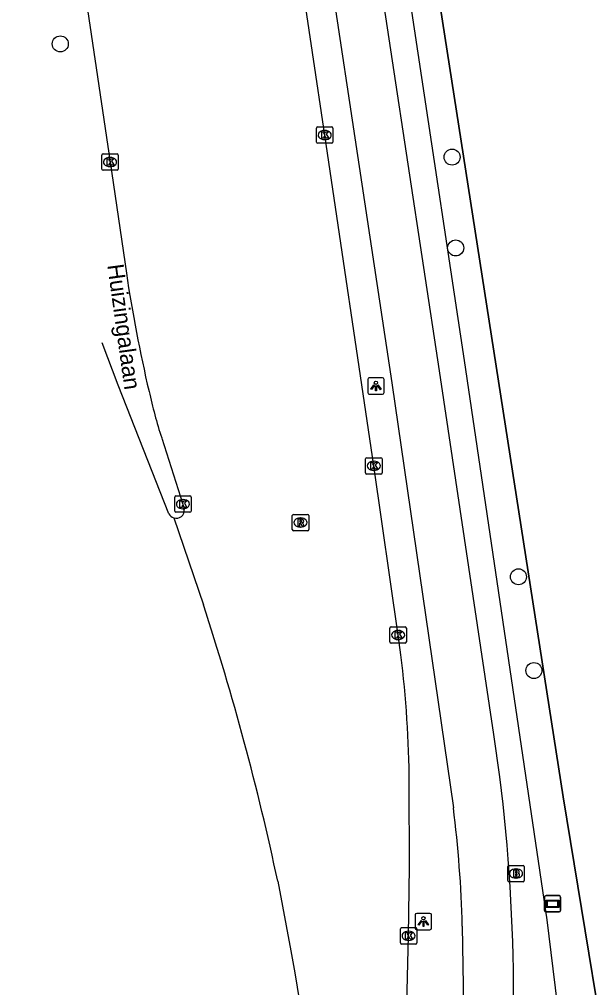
# Model space of a CAD drawing. Extents: x 159451 to 160663, y 388402 to 389723.
# Drawn here: x 159483.5 to 159518.3, y 388988.3 to 389047.5 of the extents above; entities that cross this region are included whole.
import ezdxf

# ---------------------------------------------------------------- set-up
doc = ezdxf.new("R2010")
doc.units = 0
for name, color, linetype in [('IMGEO_Boom', 7, 'Continuous'), ('IMGEO_Brandkraan', 7, 'Continuous'), ('IMGEO_Fietspad_gesloten', 7, 'Continuous'), ('IMGEO_Gemengd_bos', 7, 'Continuous'), ('IMGEO_Hek', 7, 'Continuous'), ('IMGEO_Kolk', 7, 'Continuous'), ('IMGEO_Lichtpunt', 7, 'Continuous'), ('IMGEO_Openbare_ruimte_label', 7, 'Continuous'), ('IMGEO_OVBaan_gesloten', 7, 'Continuous'), ('IMGEO_Rijbaan_regionaal_gesloten', 7, 'Continuous'), ('IMGEO_Rioolput', 7, 'Continuous'), ('IMGEO_Verklikker', 7, 'Continuous'), ('IMGEO_Voetpad_open', 7, 'Continuous')]:
    doc.layers.add(name, color=color, linetype=linetype)

msp = doc.modelspace()

# ---------------------------------------------------------------- linework, layer by layer
at = {"layer": 'IMGEO_Boom'}
for centre in [(159485.955, 389045.995), (159509.863, 389039.082), (159510.083, 389033.53), (159513.916, 389013.444), (159514.857, 389007.717)]:
    msp.add_circle(centre, 0.489, dxfattribs=at)
at = {"layer": 'IMGEO_Brandkraan'}
for p, q in [((159513.265, 388994.89), (159513.265, 388995.742)), ((159513.34, 388995.816), (159514.192, 388995.816)), ((159514.266, 388995.742), (159514.266, 388994.89)), ((159513.753, 388995.596), (159513.778, 388995.596)), ((159514.192, 388994.816), (159513.34, 388994.816)), ((159513.776, 388995.036), (159513.751, 388995.036))]:
    msp.add_line(p, q, dxfattribs=at)
for points in [[(159513.265, 388994.89), (159513.265, 388995.742)], [(159513.34, 388995.816), (159514.192, 388995.816)], [(159514.266, 388995.742), (159514.266, 388994.89)], [(159513.613, 388995.516), (159513.613, 388995.116), (159513.826, 388995.116)], [(159513.844, 388995.516), (159513.613, 388995.516)], [(159513.792, 388995.435), (159513.738, 388995.435), (159513.738, 388995.359)], [(159513.738, 388995.359), (159513.791, 388995.359)], [(159513.8, 388995.283), (159513.738, 388995.283), (159513.738, 388995.202)], [(159513.738, 388995.202), (159513.8, 388995.202)], [(159514.192, 388994.816), (159513.34, 388994.816)]]:
    msp.add_lwpolyline(points, dxfattribs=at)
for centre, radius, start, end in [((159513.342, 388995.74), 0.0765, 91.55205, 178.44795), ((159513.342, 388995.74), 0.0765, 91.55205, 178.44795), ((159514.19, 388995.74), 0.0765, 1.55205, 88.44795), ((159514.19, 388995.74), 0.0765, 1.55205, 88.44795), ((159513.793, 388995.397), 0.0379, 267.82845, 90.93552), ((159513.801, 388995.242), 0.0404, 269.87594, 90.50774), ((159513.848, 388995.371), 0.145, 59.4692, 91.53667), ((159513.873, 388995.418), 0.0922, 285.51372, 58.15012), ((159513.878, 388995.226), 0.105, 301.31148, 78.98903), ((159513.342, 388994.892), 0.0765, 181.55205, 268.44795), ((159513.342, 388994.892), 0.0765, 181.55205, 268.44795), ((159513.832, 388995.367), 0.251, 268.66757, 293.53466), ((159514.19, 388994.892), 0.0765, 271.55205, 358.44795), ((159514.19, 388994.892), 0.0765, 271.55205, 358.44795)]:
    msp.add_arc(centre, radius, start, end, dxfattribs=at)
for centre, major_axis, ratio, start_param, end_param in [((159513.752, 388995.316), (-0.387, 0.002), 0.722429, 4.712389, 7.853982), ((159513.777, 388995.316), (-0.39, 0.002), 0.717154, 1.570796, 4.712389)]:
    msp.add_ellipse(centre, major_axis=major_axis, ratio=ratio, start_param=start_param, end_param=end_param, dxfattribs=at)
at = {"layer": 'IMGEO_Fietspad_gesloten'}
for points in [[(159498.641, 389077.39), (159498.535, 389077.37), (159500.421, 389063.479), (159506.196, 389025.302), (159509.943, 388999.337)], [(159512.775, 389001.232), (159512.419, 389003.812), (159509.105, 389026.02), (159503.37, 389063.924), (159501.365, 389077.519)], [(159510.487, 388992.109), (159510.57, 388987.262), (159510.486, 388981.357), (159510.453, 388977.118), (159510.587, 388971.253)]]:
    msp.add_lwpolyline(points, dxfattribs=at)
for centre, radius, start, end in [((159405.559, 388987.753), 108.06, 0.01241, 7.16571), ((159438.669, 388990.338), 71.84, 1.4124, 7.19586)]:
    msp.add_arc(centre, radius, start, end, dxfattribs=at)
at = {"layer": 'IMGEO_Gemengd_bos'}
msp.add_lwpolyline([(159575.636, 389087.806), (159574.696, 389093.295), (159556.654, 389090.594), (159543.414, 389088.835), (159534.923, 389087.144), (159506.995, 389079.727), (159505.308, 389078.139), (159504.909, 389075.552), (159516.649, 389000), (159527.326, 388934.886), (159532.821, 388904.1), (159538.108, 388877.879)], dxfattribs=at)
at = {"layer": 'IMGEO_Hek'}
msp.add_lwpolyline([(159678.25, 388782.74), (159562.528, 388756.756), (159538.536, 388875.752), (159538.123, 388877.804), (159532.821, 388904.1), (159527.326, 388934.886), (159516.649, 389000), (159504.909, 389075.552), (159505.308, 389078.139), (159506.995, 389079.727), (159534.923, 389087.144), (159543.414, 389088.835), (159556.654, 389090.594), (159574.696, 389093.295)], dxfattribs=at)
at = {"layer": 'IMGEO_Kolk'}
for p, q in [((159501.589, 389040.004), (159501.589, 389040.856)), ((159501.664, 389040.93), (159502.516, 389040.93)), ((159502.077, 389040.71), (159502.102, 389040.71)), ((159502.59, 389040.856), (159502.59, 389040.004)), ((159502.1, 389040.15), (159502.075, 389040.15)), ((159502.516, 389039.93), (159501.664, 389039.93)), ((159488.489, 389038.355), (159488.489, 389039.207)), ((159488.564, 389039.281), (159489.416, 389039.281)), ((159488.977, 389039.061), (159489.002, 389039.061)), ((159489.49, 389039.207), (159489.49, 389038.355)), ((159489, 389038.501), (159488.975, 389038.501)), ((159489.416, 389038.281), (159488.564, 389038.281)), ((159504.588, 389019.794), (159504.588, 389020.646)), ((159504.663, 389020.72), (159505.515, 389020.72)), ((159505.589, 389020.646), (159505.589, 389019.794)), ((159505.076, 389020.5), (159505.101, 389020.5)), ((159505.515, 389019.72), (159504.663, 389019.72)), ((159505.099, 389019.94), (159505.074, 389019.94)), ((159492.939, 389017.457), (159492.939, 389018.309)), ((159493.014, 389018.383), (159493.866, 389018.383)), ((159493.94, 389018.309), (159493.94, 389017.457)), ((159493.427, 389018.163), (159493.452, 389018.163)), ((159493.866, 389017.383), (159493.014, 389017.383)), ((159493.45, 389017.603), (159493.425, 389017.603)), ((159506.072, 389009.461), (159506.072, 389010.313)), ((159506.147, 389010.387), (159506.999, 389010.387)), ((159506.56, 389010.167), (159506.585, 389010.167)), ((159507.073, 389010.313), (159507.073, 389009.461)), ((159506.999, 389009.387), (159506.147, 389009.387)), ((159506.583, 389009.607), (159506.558, 389009.607)), ((159506.708, 388991.083), (159506.708, 388991.935)), ((159506.783, 388992.009), (159507.635, 388992.009)), ((159507.196, 388991.789), (159507.221, 388991.789)), ((159507.709, 388991.935), (159507.709, 388991.083)), ((159507.635, 388991.009), (159506.783, 388991.009)), ((159507.219, 388991.229), (159507.194, 388991.229))]:
    msp.add_line(p, q, dxfattribs=at)
for points in [[(159501.589, 389040.004), (159501.589, 389040.856)], [(159501.664, 389040.93), (159502.516, 389040.93)], [(159502.59, 389040.856), (159502.59, 389040.004)], [(159501.91, 389040.63), (159502.033, 389040.63), (159502.033, 389040.479), (159502.163, 389040.63), (159502.327, 389040.63), (159502.181, 389040.479), (159502.334, 389040.23), (159502.182, 389040.23), (159502.097, 389040.394), (159502.033, 389040.327), (159502.033, 389040.23), (159501.91, 389040.23), (159501.91, 389040.63)], [(159502.516, 389039.93), (159501.664, 389039.93)], [(159488.489, 389038.355), (159488.489, 389039.207)], [(159488.564, 389039.281), (159489.416, 389039.281)], [(159488.81, 389038.981), (159488.933, 389038.981), (159488.933, 389038.83), (159489.063, 389038.981), (159489.227, 389038.981), (159489.081, 389038.83), (159489.234, 389038.581), (159489.082, 389038.581), (159488.997, 389038.745), (159488.933, 389038.678), (159488.933, 389038.581), (159488.81, 389038.581), (159488.81, 389038.981)], [(159489.49, 389039.207), (159489.49, 389038.355)], [(159489.416, 389038.281), (159488.564, 389038.281)], [(159504.588, 389019.794), (159504.588, 389020.646)], [(159504.663, 389020.72), (159505.515, 389020.72)], [(159505.589, 389020.646), (159505.589, 389019.794)], [(159504.909, 389020.42), (159505.032, 389020.42), (159505.032, 389020.269), (159505.162, 389020.42), (159505.326, 389020.42), (159505.18, 389020.269), (159505.333, 389020.02), (159505.181, 389020.02), (159505.096, 389020.184), (159505.032, 389020.117), (159505.032, 389020.02), (159504.909, 389020.02), (159504.909, 389020.42)], [(159505.515, 389019.72), (159504.663, 389019.72)], [(159492.939, 389017.457), (159492.939, 389018.309)], [(159493.014, 389018.383), (159493.866, 389018.383)], [(159493.94, 389018.309), (159493.94, 389017.457)], [(159493.26, 389018.083), (159493.383, 389018.083), (159493.383, 389017.932), (159493.513, 389018.083), (159493.677, 389018.083), (159493.531, 389017.932), (159493.684, 389017.683), (159493.532, 389017.683), (159493.447, 389017.847), (159493.383, 389017.78), (159493.383, 389017.683), (159493.26, 389017.683), (159493.26, 389018.083)], [(159493.866, 389017.383), (159493.014, 389017.383)], [(159506.072, 389009.461), (159506.072, 389010.313)], [(159506.147, 389010.387), (159506.999, 389010.387)], [(159506.393, 389010.087), (159506.516, 389010.087), (159506.516, 389009.936), (159506.646, 389010.087), (159506.81, 389010.087), (159506.664, 389009.936), (159506.817, 389009.687), (159506.665, 389009.687), (159506.58, 389009.851), (159506.516, 389009.784), (159506.516, 389009.687), (159506.393, 389009.687), (159506.393, 389010.087)], [(159507.073, 389010.313), (159507.073, 389009.461)], [(159506.999, 389009.387), (159506.147, 389009.387)], [(159506.708, 388991.083), (159506.708, 388991.935)], [(159506.783, 388992.009), (159507.635, 388992.009)], [(159507.029, 388991.709), (159507.152, 388991.709), (159507.152, 388991.558), (159507.282, 388991.709), (159507.446, 388991.709), (159507.3, 388991.558), (159507.453, 388991.309), (159507.301, 388991.309), (159507.216, 388991.473), (159507.152, 388991.406), (159507.152, 388991.309), (159507.029, 388991.309), (159507.029, 388991.709)], [(159507.709, 388991.935), (159507.709, 388991.083)], [(159507.635, 388991.009), (159506.783, 388991.009)]]:
    msp.add_lwpolyline(points, dxfattribs=at)
for centre, start, end in [((159501.666, 389040.854), 91.55205, 178.44795), ((159501.666, 389040.854), 91.55205, 178.44795), ((159502.514, 389040.854), 1.55205, 88.44795), ((159502.514, 389040.854), 1.55205, 88.44795), ((159501.666, 389040.006), 181.55205, 268.44795), ((159501.666, 389040.006), 181.55205, 268.44795), ((159502.514, 389040.006), 271.55205, 358.44795), ((159502.514, 389040.006), 271.55205, 358.44795), ((159488.566, 389039.205), 91.55205, 178.44795), ((159488.566, 389039.205), 91.55205, 178.44795), ((159489.414, 389039.205), 1.55205, 88.44795), ((159489.414, 389039.205), 1.55205, 88.44795), ((159488.566, 389038.357), 181.55205, 268.44795), ((159488.566, 389038.357), 181.55205, 268.44795), ((159489.414, 389038.357), 271.55205, 358.44795), ((159489.414, 389038.357), 271.55205, 358.44795), ((159504.665, 389020.644), 91.55205, 178.44795), ((159504.665, 389020.644), 91.55205, 178.44795), ((159505.513, 389020.644), 1.55205, 88.44795), ((159505.513, 389020.644), 1.55205, 88.44795), ((159504.665, 389019.796), 181.55205, 268.44795), ((159504.665, 389019.796), 181.55205, 268.44795), ((159505.513, 389019.796), 271.55205, 358.44795), ((159505.513, 389019.796), 271.55205, 358.44795), ((159493.016, 389018.307), 91.55205, 178.44795), ((159493.016, 389018.307), 91.55205, 178.44795), ((159493.864, 389018.307), 1.55205, 88.44795), ((159493.864, 389018.307), 1.55205, 88.44795), ((159493.016, 389017.459), 181.55205, 268.44795), ((159493.016, 389017.459), 181.55205, 268.44795), ((159493.864, 389017.459), 271.55205, 358.44795), ((159493.864, 389017.459), 271.55205, 358.44795), ((159506.149, 389010.311), 91.55205, 178.44795), ((159506.149, 389010.311), 91.55205, 178.44795), ((159506.997, 389010.311), 1.55205, 88.44795), ((159506.997, 389010.311), 1.55205, 88.44795), ((159506.149, 389009.463), 181.55205, 268.44795), ((159506.149, 389009.463), 181.55205, 268.44795), ((159506.997, 389009.463), 271.55205, 358.44795), ((159506.997, 389009.463), 271.55205, 358.44795), ((159506.785, 388991.933), 91.55205, 178.44795), ((159506.785, 388991.933), 91.55205, 178.44795), ((159507.633, 388991.933), 1.55205, 88.44795), ((159507.633, 388991.933), 1.55205, 88.44795), ((159506.785, 388991.085), 181.55205, 268.44795), ((159506.785, 388991.085), 181.55205, 268.44795), ((159507.633, 388991.085), 271.55205, 358.44795), ((159507.633, 388991.085), 271.55205, 358.44795)]:
    msp.add_arc(centre, 0.0765, start, end, dxfattribs=at)
for centre, major_axis, ratio, start_param, end_param in [((159502.076, 389040.43), (-0.387, 0.002), 0.722429, 4.712389, 7.853982), ((159502.101, 389040.43), (-0.39, 0.002), 0.717154, 1.570796, 4.712389), ((159488.976, 389038.781), (-0.387, 0.002), 0.722429, 4.712389, 7.853982), ((159489.001, 389038.781), (-0.39, 0.002), 0.717154, 1.570796, 4.712389), ((159505.075, 389020.22), (-0.387, 0.002), 0.722429, 4.712389, 7.853982), ((159505.1, 389020.22), (-0.39, 0.002), 0.717154, 1.570796, 4.712389), ((159493.426, 389017.883), (-0.387, 0.002), 0.722429, 4.712389, 7.853982), ((159493.451, 389017.883), (-0.39, 0.002), 0.717154, 1.570796, 4.712389), ((159506.559, 389009.887), (-0.387, 0.002), 0.722429, 4.712389, 7.853982), ((159506.584, 389009.887), (-0.39, 0.002), 0.717154, 1.570796, 4.712389), ((159507.195, 388991.509), (-0.387, 0.002), 0.722429, 4.712389, 7.853982), ((159507.22, 388991.509), (-0.39, 0.002), 0.717154, 1.570796, 4.712389)]:
    msp.add_ellipse(centre, major_axis=major_axis, ratio=ratio, start_param=start_param, end_param=end_param, dxfattribs=at)
at = {"layer": 'IMGEO_Lichtpunt'}
for p, q in [((159504.719, 389025.501), (159504.719, 389024.694)), ((159504.719, 389025.501), (159504.719, 389024.694)), ((159505.621, 389025.596), (159504.813, 389025.596)), ((159505.621, 389025.596), (159504.813, 389025.596)), ((159505.715, 389024.694), (159505.715, 389025.501)), ((159505.715, 389024.694), (159505.715, 389025.501)), ((159504.813, 389024.6), (159505.621, 389024.6)), ((159504.813, 389024.6), (159505.621, 389024.6)), ((159507.614, 388992.785), (159507.614, 388991.978)), ((159507.614, 388992.785), (159507.614, 388991.978)), ((159508.516, 388992.88), (159507.708, 388992.88)), ((159508.516, 388992.88), (159507.708, 388992.88)), ((159508.61, 388991.978), (159508.61, 388992.785)), ((159508.61, 388991.978), (159508.61, 388992.785)), ((159507.708, 388991.884), (159508.516, 388991.884)), ((159507.708, 388991.884), (159508.516, 388991.884))]:
    msp.add_line(p, q, dxfattribs=at)
for points in [[(159505.093, 389025.165), (159505.132, 389025.137), (159504.944, 389024.875), (159504.906, 389024.902), (159505.093, 389025.165)], [(159505.195, 389025.117), (159505.242, 389025.117), (159505.242, 389024.795), (159505.195, 389024.795), (159505.195, 389025.117)], [(159505.305, 389025.137), (159505.343, 389025.164), (159505.53, 389024.902), (159505.491, 389024.874), (159505.305, 389025.137)], [(159507.988, 388992.449), (159508.027, 388992.421), (159507.839, 388992.159), (159507.801, 388992.186), (159507.988, 388992.449)], [(159508.09, 388992.401), (159508.137, 388992.401), (159508.137, 388992.079), (159508.09, 388992.079), (159508.09, 388992.401)], [(159508.2, 388992.421), (159508.238, 388992.448), (159508.425, 388992.186), (159508.386, 388992.158), (159508.2, 388992.421)]]:
    msp.add_lwpolyline(points, dxfattribs=at)
for centre in [(159505.218, 389025.299), (159508.113, 388992.583)]:
    msp.add_circle(centre, 0.0994, dxfattribs=at)
for centre, start, end in [((159504.813, 389025.501), 90, 180), ((159504.813, 389025.501), 90, 180), ((159505.621, 389025.501), 0, 90), ((159505.621, 389025.501), 0, 90), ((159504.813, 389024.694), 180, 270), ((159504.813, 389024.694), 180, 270), ((159505.621, 389024.694), 270, 0), ((159505.621, 389024.694), 270, 360), ((159507.708, 388992.785), 90, 180), ((159507.708, 388992.785), 90, 180), ((159508.516, 388992.785), 0, 90), ((159508.516, 388992.785), 0, 90), ((159507.708, 388991.978), 180, 270), ((159507.708, 388991.978), 180, 270), ((159508.516, 388991.978), 270, 0), ((159508.516, 388991.978), 270, 360)]:
    msp.add_arc(centre, 0.0946, start, end, dxfattribs=at)
at = {"layer": 'IMGEO_OVBaan_gesloten'}
for points in [[(159492.585, 389017.295), (159489.48, 389025.155), (159488.502, 389027.728)], [(159492.882, 389017.041), (159494.69, 389011.738)], [(159499.228, 388994.844), (159500.031, 388990.584), (159500.266, 388989.259), (159503.761, 388967.731), (159507.601, 388945.012), (159510.836, 388926.495), (159514.579, 388905.283), (159517.659, 388888.539), (159521.554, 388867.599), (159524.959, 388849.753), (159528.539, 388831.763), (159531.945, 388815.103), (159535.343, 388798.849), (159538.98, 388781.958), (159541.749, 388769.516)]]:
    msp.add_lwpolyline(points, dxfattribs=at)
for centre, radius, start, end in [((159493.024, 389017.508), 0.488, 205.88382, 253.04081), ((159336.91, 388960.299), 165.953, 12.01451, 18.05678)]:
    msp.add_arc(centre, radius, start, end, dxfattribs=at)
at = {"layer": 'IMGEO_Rijbaan_regionaal_gesloten'}
for points in [[(159506.742, 389008.683), (159506.573, 389009.887), (159505.089, 389020.22), (159502.09, 389040.43), (159499.086, 389060.633), (159497.993, 389067.961), (159496.731, 389076.306), (159496.535, 389078.187)], [(159483.459, 389076.149), (159483.743, 389074.245), (159486.154, 389057.989), (159488.99, 389038.781), (159489.988, 389032)], [(159492.144, 389021.922), (159493.44, 389017.883), (159493.524, 389017.562)], [(159506.819, 388973.728), (159506.882, 388978.092), (159507.209, 388991.509), (159507.271, 388995.718), (159507.254, 389000.815)]]:
    msp.add_lwpolyline(points, dxfattribs=at)
for centre, radius, start, end in [((159576.305, 389044.767), 87.256, 188.41335, 193.24774), ((159520.115, 389031.041), 29.42, 192.30449, 198.05595), ((159493.03, 389017.515), 0.497, 252.69256, 5.42793), ((159436.93, 389000.189), 70.327, 0.5097, 6.9367)]:
    msp.add_arc(centre, radius, start, end, dxfattribs=at)
at = {"layer": 'IMGEO_Rioolput'}
for p, q in [((159500.113, 389016.33), (159500.113, 389017.182)), ((159500.188, 389017.256), (159501.04, 389017.256)), ((159500.601, 389017.036), (159500.626, 389017.036)), ((159501.114, 389017.182), (159501.114, 389016.33)), ((159500.624, 389016.476), (159500.599, 389016.476)), ((159501.04, 389016.256), (159500.188, 389016.256))]:
    msp.add_line(p, q, dxfattribs=at)
for points in [[(159500.113, 389016.33), (159500.113, 389017.182)], [(159500.188, 389017.256), (159501.04, 389017.256)], [(159501.114, 389017.182), (159501.114, 389016.33)], [(159500.702, 389016.954), (159500.45, 389016.956), (159500.45, 389016.556)], [(159500.45, 389016.556), (159500.574, 389016.556), (159500.574, 389016.718), (159500.585, 389016.718)], [(159500.628, 389016.875), (159500.574, 389016.875), (159500.574, 389016.794)], [(159500.574, 389016.794), (159500.626, 389016.794)], [(159500.632, 389016.689), (159500.703, 389016.556), (159500.843, 389016.556), (159500.778, 389016.682)], [(159501.04, 389016.256), (159500.188, 389016.256)]]:
    msp.add_lwpolyline(points, dxfattribs=at)
for centre, radius, start, end in [((159500.19, 389017.18), 0.0765, 91.55205, 178.44795), ((159500.19, 389017.18), 0.0765, 91.55205, 178.44795), ((159501.038, 389017.18), 0.0765, 1.55205, 88.44795), ((159501.038, 389017.18), 0.0765, 1.55205, 88.44795), ((159500.584, 389016.665), 0.0533, 26.02933, 88.69889), ((159500.61, 389016.983), 0.19, 274.7715, 282.96867), ((159500.634, 389016.779), 0.0964, 77.00612, 93.18647), ((159500.648, 389016.836), 0.0378, 276.66336, 79.67722), ((159500.701, 389016.844), 0.109, 350.36119, 89.41601), ((159500.699, 389016.844), 0.112, 277.58423, 350.98172), ((159500.683, 389016.629), 0.108, 29.51342, 73.79051), ((159500.19, 389016.332), 0.0765, 181.55205, 268.44795), ((159500.19, 389016.332), 0.0765, 181.55205, 268.44795), ((159501.038, 389016.332), 0.0765, 271.55205, 358.44795), ((159501.038, 389016.332), 0.0765, 271.55205, 358.44795)]:
    msp.add_arc(centre, radius, start, end, dxfattribs=at)
for centre, major_axis, ratio, start_param, end_param in [((159500.6, 389016.756), (-0.387, 0.002), 0.722429, 4.712389, 7.853982), ((159500.625, 389016.756), (-0.39, 0.002), 0.717154, 1.570796, 4.712389)]:
    msp.add_ellipse(centre, major_axis=major_axis, ratio=ratio, start_param=start_param, end_param=end_param, dxfattribs=at)
at = {"layer": 'IMGEO_Verklikker'}
for p, q in [((159515.599, 388993.967), (159516.389, 388993.967)), ((159516.389, 388993.967), (159515.599, 388993.967)), ((159515.499, 388993.067), (159515.499, 388993.867)), ((159515.499, 388993.867), (159515.499, 388993.067)), ((159516.489, 388993.867), (159516.489, 388993.067)), ((159516.489, 388993.067), (159516.489, 388993.867)), ((159516.389, 388992.967), (159515.599, 388992.967)), ((159515.599, 388992.967), (159516.389, 388992.967))]:
    msp.add_line(p, q, dxfattribs=at)
for points in [[(159515.6, 388993.699), (159516.388, 388993.699), (159516.388, 388993.235), (159515.6, 388993.235), (159515.6, 388993.699)], [(159515.665, 388993.634), (159515.665, 388993.3), (159516.323, 388993.3), (159516.323, 388993.634), (159515.665, 388993.634)]]:
    msp.add_lwpolyline(points, dxfattribs=at)
for centre, start, end in [((159515.599, 388993.867), 90, 180), ((159515.599, 388993.867), 90, 180), ((159516.389, 388993.867), 0, 90), ((159516.389, 388993.867), 360, 90), ((159515.599, 388993.067), 180, 270), ((159515.599, 388993.067), 180, 270), ((159516.389, 388993.067), 270, 0), ((159516.389, 388993.067), 270, 0)]:
    msp.add_arc(centre, 0.1, start, end, dxfattribs=at)
at = {"layer": 'IMGEO_Voetpad_open'}
msp.add_lwpolyline([(159503.082, 389076.792), (159504.945, 389064.234), (159510.601, 389026.663), (159515.653, 388992.482), (159516.512, 388985.346), (159517.252, 388980.028), (159520.19, 388962.941), (159524.008, 388940.78), (159527.88, 388918.773), (159530.761, 388903.029), (159535.59, 388877.415), (159538.108, 388877.879)], dxfattribs=at)

# ---------------------------------------------------------------- texts
at = {"layer": 'IMGEO_Openbare_ruimte_label'}
msp.add_text('Huizingalaan', height=1, rotation=277.87092, dxfattribs=at).set_placement((159488.821, 389032.483))

doc.saveas('drawing.dxf')
